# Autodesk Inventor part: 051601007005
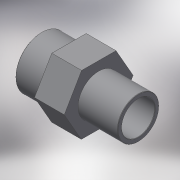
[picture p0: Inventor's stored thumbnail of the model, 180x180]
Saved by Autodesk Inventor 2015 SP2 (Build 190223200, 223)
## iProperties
Created: 2017-10
Part Number: 051601007005
Material: Generic
Description: PLASSON THR. REDUCING NIPPLE 3/4"-1/2" PVC
Document SubType Name: Modeling
Designer: KIM
Density: 1 g/cm^3
Appearance: Default
Author: KIM
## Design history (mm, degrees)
derived "051601.ipt"
feature "Solid1::051601.ipt"
tag "TaggingFeature1"
body "Solid1"
other parameters: "d13" = 0, "d14" = 0.20955, "d17" = 11, "d18" = 20.4, "d19" = 26.441, "d21" = 20.955, "d23" = 21.1528, "d24" = 16.764, "d25" = 17, "d26" = -11, "R_1" = 20.955, "lt_1" = 11, "lt_" = 17, "R_" = 26.441
